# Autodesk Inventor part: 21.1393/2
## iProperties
Created: 2006-12
Part Number: 21.1393/2
Document SubType Name: Modeling
Designer: Andy Moles
Material: Steel
Density: 7.85 g/cm^3
Mass: 14.3742 g
Surface Area: 18.2508 cm^2
Volume: 1.83111 cm^3
Vendor: S
Description: POWER-LOCK BODY
Author: Andy Moles
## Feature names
1. Extrusion1
2. Extrusion2
3. Mirror1
4. Extrusion3
5. Extrusion4
6. Extrusion5
